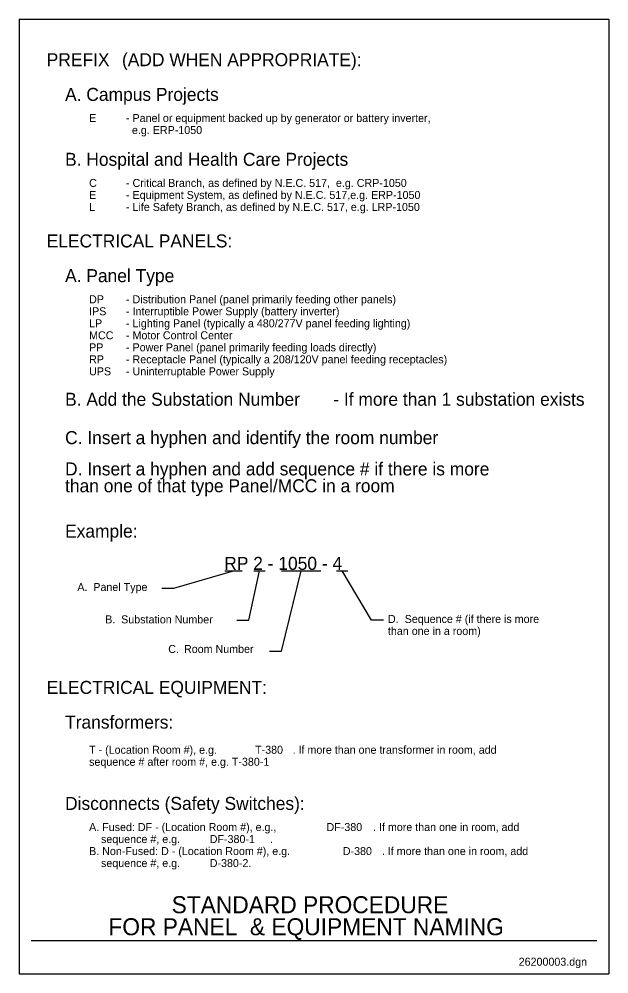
# Model space of a CAD drawing. Extents: x 10141.1 to 10190.2, y 10021.4 to 10100.9.
import ezdxf

# ---------------------------------------------------------------- set-up
doc = ezdxf.new("R2010")
doc.units = 0
doc.layers.add('Default', color=7, linetype='Continuous')
doc.layers.add('G-ANNO-TEXT', color=7, linetype='Continuous')

msp = doc.modelspace()

# ---------------------------------------------------------------- linework, layer by layer
at = {"layer": 'Default'}
for p, q in [((10141.086, 10100.911), (10190.228, 10100.911)), ((10141.086, 10100.911), (10141.086, 10066.884)), ((10190.228, 10100.911), (10190.228, 10066.884)), ((10141.086, 10066.884), (10141.086, 10021.384)), ((10190.228, 10066.884), (10190.228, 10021.384)), ((10142.084, 10024.172), (10189.23, 10024.172)), ((10141.086, 10021.384), (10190.228, 10021.384))]:
    msp.add_line(p, q, dxfattribs=at)
at = {"layer": 'G-ANNO-TEXT'}
for p, q in [((10158.236, 10054.944), (10159.679, 10054.944)), ((10160.633, 10054.944), (10161.586, 10054.944)), ((10162.948, 10054.944), (10166.217, 10054.944)), ((10167.531, 10054.944), (10168.468, 10054.944))]:
    msp.add_line(p, q, dxfattribs=at)
for points in [[(10152.984, 10053.503), (10153.984, 10053.503), (10158.958, 10054.944)], [(10159.219, 10050.845), (10160.219, 10050.845), (10161.11, 10054.944)], [(10161.955, 10048.265), (10162.955, 10048.265), (10164.583, 10054.944)], [(10171.444, 10050.845), (10170.444, 10050.845), (10168, 10054.944)]]:
    msp.add_lwpolyline(points, dxfattribs=at)

# ---------------------------------------------------------------- texts
at = {"layer": 'Default'}
for s, height, p in [('STANDARD PROCEDURE', 1.41667, (10153.797, 10026.438)), ('FOR PANEL  & EQUIPMENT NAMING', 1.41667, (10148.53, 10024.605)), ('26200003.dgn', 0.66667, (10182.709, 10022.066))]:
    msp.add_text(s, height=height, dxfattribs=at).set_placement(p)
at = {"layer": 'G-ANNO-TEXT'}
for s, height, p in [('PREFIX', 1.0833, (10143.387, 10096.99)), ('  (ADD WHEN APPROPRIATE):', 1.08333, (10148.855, 10096.99)), ('A. Campus Projects', 1.08333, (10144.918, 10094.097)), ('E', 0.667, (10146.919, 10092.337)), ('- Panel or equipment backed up by generator or battery inverter,', 0.66667, (10149.994, 10092.337)), ('  e.g. ERP-1050', 0.66667, (10149.994, 10091.337)), ('B. Hospital and Health Care Projects', 1.08333, (10144.918, 10088.69)), ('C', 0.667, (10146.919, 10086.93)), ('- Critical Branch, as defined by N.E.C. 517,  e.g. CRP-1050', 0.66667, (10149.994, 10086.93)), ('E', 0.667, (10146.919, 10085.93)), ('- Equipment System, as defined by N.E.C. 517,e.g. ERP-1050', 0.66667, (10149.994, 10085.93)), ('L', 0.667, (10146.919, 10084.93)), ('- Life Safety Branch, as defined by N.E.C. 517, e.g. LRP-1050', 0.66667, (10149.994, 10084.93)), ('ELECTRICAL PANELS:', 1.08333, (10143.387, 10081.893)), ('A. Panel Type', 1.08333, (10144.918, 10079.001)), ('DP', 0.6667, (10146.919, 10077.241)), ('- Distribution Panel (panel primarily feeding other panels)', 0.66667, (10149.994, 10077.241)), ('IPS', 0.6667, (10146.919, 10076.241)), ('- Interruptible Power Supply (battery inverter)', 0.66667, (10149.994, 10076.241)), ('LP', 0.6667, (10146.919, 10075.241)), ('- Lighting Panel (typically a 480/277V panel feeding lighting)', 0.66667, (10149.994, 10075.241)), ('MCC', 0.6667, (10146.919, 10074.241)), ('- Motor Control Center', 0.66667, (10149.994, 10074.241)), ('PP', 0.6667, (10146.919, 10073.241)), ('- Power Panel (panel primarily feeding loads directly)', 0.66667, (10149.994, 10073.241)), ('- Receptacle Panel (typically a 208/120V panel feeding receptacles)', 0.66667, (10149.994, 10072.241)), ('RP', 0.6667, (10146.919, 10072.241)), ('UPS', 0.6667, (10146.919, 10071.241)), ('- Uninterruptable Power Supply', 0.66667, (10149.994, 10071.241)), ('B. Add the Substation Number', 1.08333, (10144.918, 10068.705)), (' - If more than 1 substation exists', 1.08333, (10166.863, 10068.705)), ('C. Insert a hyphen and identify the room number', 1.08333, (10144.918, 10065.508)), ('D. Insert a hyphen and add sequence # if there is more', 1.08333, (10144.918, 10062.904)), ('than one of that type Panel/MCC in a room', 1.08333, (10144.918, 10061.502)), ('Example:', 1.0833, (10144.918, 10057.723)), ('RP 2 - 1050 - 4', 1.08333, (10158.178, 10055.034)), ('A.', 0.6667, (10145.942, 10053.274)), (' Panel Type', 0.66667, (10147.023, 10053.274)), ('B.', 0.6667, (10148.261, 10050.578)), (' Substation Number', 0.66667, (10149.342, 10050.578)), ('D.', 0.6667, (10171.817, 10050.615)), (' Sequence # (if there is more', 0.66667, (10172.965, 10050.615)), ('than one in a room)', 0.66667, (10171.817, 10049.615)), ('C.', 0.6667, (10153.513, 10048.114)), (' Room Number', 0.66667, (10154.578, 10048.114)), ('ELECTRICAL EQUIPMENT:', 1.08333, (10143.387, 10044.706)), ('Transformers:', 1.08333, (10144.918, 10041.814)), ('T - (Location Room #), e.g. ', 0.66667, (10146.919, 10039.72)), ('T-380', 0.6667, (10160.747, 10039.72)), ('. If more than one transformer in room, add', 0.66667, (10163.873, 10039.72)), ('sequence # after room #, e.g. T-380-1', 0.66667, (10146.919, 10038.72)), ('Disconnects (Safety Switches):', 1.08333, (10144.918, 10035.042)), ('A. Fused: DF - (Location Room #), e.g., ', 0.66667, (10146.919, 10033.282)), ('. If more than one in room, add', 0.66667, (10170.576, 10033.282)), ('DF-380', 0.6667, (10166.701, 10033.282)), ('    sequence #, e.g. ', 0.66667, (10146.919, 10032.282)), ('DF-380-1', 0.6667, (10156.971, 10032.282)), ('.', 0.667, (10161.991, 10032.282)), ('B. Non-Fused: D - (Location Room #), e.g. ', 0.66667, (10146.919, 10031.282)), ('D-380', 0.6667, (10168.056, 10031.282)), ('. If more than one in room, add', 0.66667, (10171.314, 10031.282)), ('    sequence #, e.g. ', 0.66667, (10146.919, 10030.282)), ('D-380-2.', 0.6667, (10156.971, 10030.282))]:
    msp.add_text(s, height=height, dxfattribs=at).set_placement(p)

doc.saveas('drawing.dxf')
